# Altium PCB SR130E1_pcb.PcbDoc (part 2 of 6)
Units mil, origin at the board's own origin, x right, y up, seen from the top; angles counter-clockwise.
Board outline 5700 x 4800 mil, 6 copper layers (Top Layer, Signal Layer 1, Signal Layer 2, Signal Layer 3, Signal Layer 4, Bottom Layer), stack 61.4 mil thick; 452 components, 288 nets, 1391 pads, 911 vias.
Unrouted connection lines stored in the file: 523.
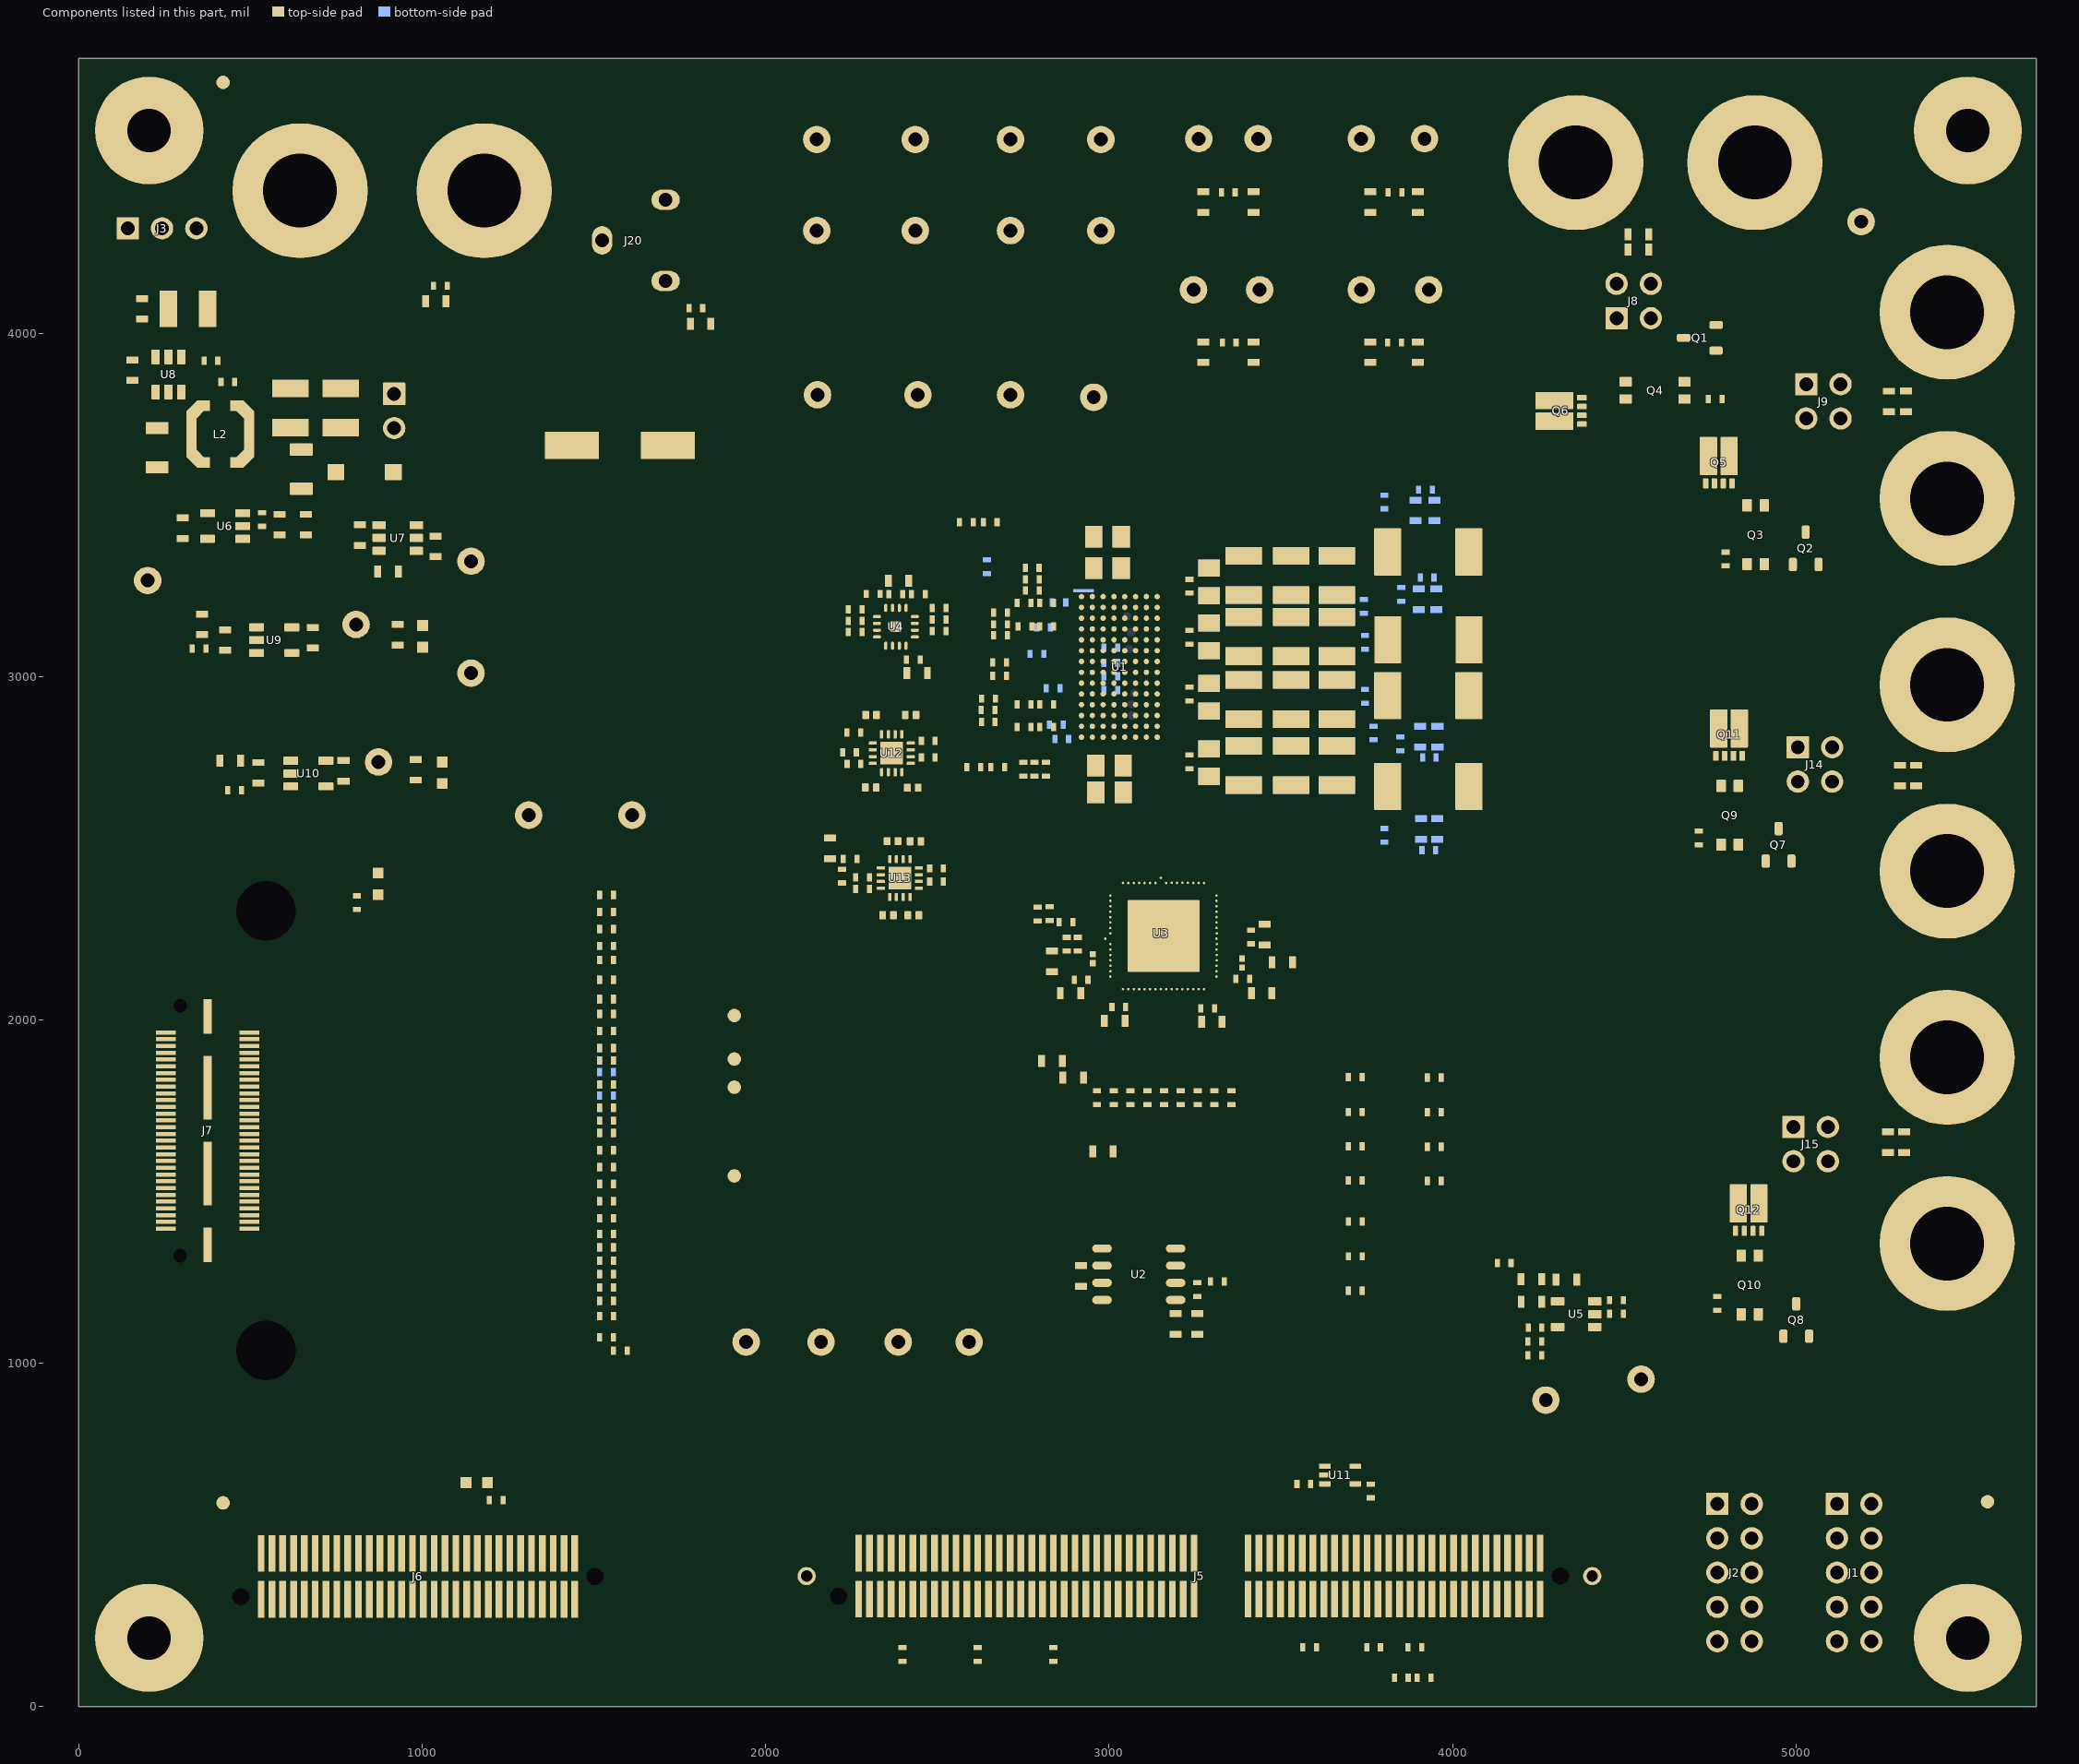
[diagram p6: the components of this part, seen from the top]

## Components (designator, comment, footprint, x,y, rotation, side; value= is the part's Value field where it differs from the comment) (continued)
R165 "CRCW040222R0JNED" 0402S 1537.09,2215.27 r180 top value=22
R166 "CRCW040222R0JNED" 0402S 1537.09,2264.82 r180 top value=22
R167 "CRCW040222R0JNED" 0402S 1537.09,2314.38 r180 top value=22
R168 "CRCW040222R0JNED" 0402S 1537.09,2363.94 r180 top value=22
R169 "ERA-2AEB102X" 0402S 810,2341.09 r270 top value=1.00k
R170 "CRCW040222R0JNED" 0402S 1537.09,1136.86 r0 top value=22
R171 "CRCW040222R0JNED" 0402S 1537.09,1181.96 r0 top value=22
R172 "CRCW040222R0JNED" 0402S 1537.09,1220.76 r0 top value=22
R173 "CRCW040222R0JNED" 0402S 1537.09,1259.57 r0 top value=22
R174 "CRCW040222R0JNED" 0402S 1537.09,1298.37 r0 top value=22
R175 "CRCW040222R0JNED" 0402S 1537.09,1337.17 r0 top value=22
R176 "CRCW040222R0JNED" 0402S 1537.09,1375.98 r0 top value=22
R177 "CRCW040210K0FKED" 0402S 1537.16,1075.74 r0 top value=10.0k
R178 "CRCW040210K0FKED" 0402S 1577.16,1036.74 r0 top value=10.0k
R179 "CRCW0402150RFKED" 0402S 4765.24,3808.24 r0 top value=150
R180 "CRCW0402150RFKED" 0402S 4794.85,3342.02 r90 top value=150
R181 "CRCW0402150RFKED" 0402S 4717.32,2529.51 r90 top value=150
R182 "CRCW0402150RFKED" 0402S 4771.02,1174.56 r90 top value=150
R183 "CRCW04020000Z0ED" 0402S 2256.86,2836.21 r180 top value=0
R184 "CRCW04020000Z0ED" 0402S 2473.63,2764.07 r0 top value=0
R185 "CRCW04020000Z0ED" 0402S 2473.63,2812.05 r0 top value=0
R186 "CRCW04020000Z0ED" 0402S 2257.36,2745.52 r180 top value=0
R187 "RT0603BRD0710KL" 0603S 2187.16,2499.47 r270 top value=10.0k
R188 "CRCW0402866RFKED" 0402S 2223.16,2418.62 r90 top value=866
R189 "CRCW04020000Z0ED" 0402S 2246.37,2468.39 r180 top value=0
R190 "CRCW04020000Z0ED" 0402S 2497.98,2402.93 r0 top value=0
R191 "CRCW04020000Z0ED" 0402S 2497.98,2441.05 r0 top value=0
R192 "CRCW04020000Z0ED" 0402S 2282.79,2380.87 r180 top value=0
SH-J1 "60900213421" Wurth_60900213421 295.19,4304.95 r0 top
SH-J2 "60900213421" Wurth_60900213421 918.65,3773.18 r90 top
SH-J3 "60900213421" Wurth_60900213421 5080.41,3857.59 r180 top
SH-J4 "60900213421" Wurth_60900213421 5081.16,3738.6 r180 top
SH-J5 "60900213421" Wurth_60900213421 4590,4093.27 r90 top
SH-J6 "60900213421" Wurth_60900213421 5043.38,1697.08 r180 top
SH-J7 "60900213421" Wurth_60900213421 5057.41,2685.87 r180 top
SH-J8 "60900213421" Wurth_60900213421 5058.09,2807.52 r180 top
SH-J9 "60900213421" Wurth_60900213421 4467.79,4093.27 r90 top
SH-J10 "60900213421" Wurth_60900213421 5042.98,1573 r180 top
TP1 "5000" Keystone5000 3261.15,4566.08 r90 top
TP2 "5001" Keystone5001 3434.13,4566.08 r90 top
TP3 "SYNC" Keystone5004 2713.15,3820.18 r90 top
TP4 "AGND" Keystone5001 2443.41,3820.18 r90 top
TP5 "5000" Keystone5000 3246.05,4126.08 r90 top
TP6 "5001" Keystone5001 3438.75,4126.08 r90 top
TP7 "SYNC_OUT" Keystone5004 2151.38,3820.18 r90 top
TP8 "5000" Keystone5000 3734.37,4566.08 r90 top
TP9 "5001" Keystone5001 3918.76,4566.08 r90 top
TP10 "5001" Keystone5001 2955.47,3813.25 r0 top
TP11 "5001" Keystone5001 5189.9,4324.34 r0 top
TP12 "5000" Keystone5000 3734.37,4126.08 r90 top
TP13 "5001" Keystone5001 3930.99,4126.08 r90 top
TP14 "LSEN1+" Keystone5004 2149.07,4563.77 r90 top
TP15 "LSEN3+" Keystone5004 2713.15,4563.77 r90 top
TP16 "LSEN2+" Keystone5004 2435.98,4563.77 r90 top
TP17 "LSEN4+" Keystone5004 2976.27,4563.77 r90 top
TP18 "5001" Keystone5001 2149.07,4298.34 r0 top
TP19 "5001" Keystone5001 2435.98,4298.34 r0 top
TP20 "5001" Keystone5001 2713.15,4298.34 r0 top
TP21 "5001" Keystone5001 2976.27,4298.34 r0 top
TP22 "TP_SM_1MM" TP_SM_1MM 1908.94,1885.63 r0 top
TP23 "TP_SM_1MM" TP_SM_1MM 1908.94,1545.46 r0 top
TP24 "TP_SM_1MM" TP_SM_1MM 1908.94,2012.51 r90 top
TP25 "TP_SM_1MM" TP_SM_1MM 1908.94,1803.66 r90 top
TP26 "5000" Keystone5000 1611.19,2596.17 r0 top
TP27 "5000" Keystone5000 4271.89,892.68 r90 top
TP28 "5001" Keystone5001 4549.33,953.44 r0 top
TP29 "5000" Keystone5000 200.79,3279.56 r270 top
TP30 "5000" Keystone5000 1142.39,3335.51 r0 top
TP31 "5000" Keystone5000 807.72,3151.35 r90 top
TP32 "5000" Keystone5000 872.97,2750.87 r90 top
TP33 "5001" Keystone5001 1943.28,1061.66 r90 top
TP34 "5001" Keystone5001 1310.34,2596.17 r90 top
TP35 "5001" Keystone5001 2592.83,1061.66 r90 top
TP36 "5001" Keystone5001 2386.33,1061.66 r90 top
TP37 "5001" Keystone5001 2161.65,1061.66 r90 top
TP38 "5001" Keystone5001 1142.39,3009.58 r90 top
U1 "TPSM8F7620AOGR" APG0112A-MFG 3030.07,3027.87 r90 top
U2 "REF5040AIDR" D0008A_N 3086.96,1259.14 r0 top
U3 "ADS9324RSK" RSK0064B-MFG 3158.7,2244.06 r270 top
U4 "DAC80508MRTET" RTE0016D 2379.47,3144.61 r180 top
U5 "OPA192IDBVT" DBV0005A_N 4360.51,1142.68 r180 top
U6 "TPS7A2050PDBVR" DBV0005A-MFG 426.32,3438.02 r180 top
U7 "LM2664M6" DBV0006A_N 929.09,3403.33 r180 top
U8 "LMR54410DBVR" DBV0006A-MFG 261.28,3879.5 r90 top
U9 "TPS7A2033PDBVR" DBV0005A-MFG 569.38,3105.86 r0 top
U10 "TPS7A2018PDBVR" DBV0005A-MFG 668.88,2717.4 r0 top
U11 "TMP235DCK" DCK0005A_N 3673.04,674.26 r0 top
U12 "OPA4990IRTER" RTE0016C-MFG 2367.3,2776.48 r0 top
U13 "OPA4990IRTER" RTE0016C-MFG 2390.91,2412.78 r0 top
ZZ1 "This Assembly Note is for PCB labels only" AssemblyNoteLabel 469.91,-566 r0 top
ZZ2 "These assemblies are ESD sensitive, ESD precautions shall be observed." AssemblyNote 469.91,-666 r0 top
ZZ3 "These assemblies must be clean and free from flux and all contaminants. Use of no clean flux is not acceptable." AssemblyNote 469.91,-766 r0 top
ZZ4 "These assemblies must comply with workmanship standards IPC-A-610 Class 2, unless otherwise specified." AssemblyNote 469.91,-866 r0 top

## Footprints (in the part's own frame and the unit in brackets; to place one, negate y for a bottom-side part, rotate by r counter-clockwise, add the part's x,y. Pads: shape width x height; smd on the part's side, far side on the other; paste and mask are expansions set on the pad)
0201 [mm] "Data from Kemet datasheet CC101_COM dated 7/28/11"
  rect 0.46x0.42 smd: 1(-0.33,0) 2(0.33,0)
  silkscreen extent -0.25,-0.41 0.25,0.41, body extent -0.31,-0.16 0.31,0.16, height 0.26
0402S [mil] "Based on C0402S footprint from PADS legacy"
  rect 15x24 smd: 1(-20,0) 2(20,0)
  body extent -22,-12 22,12, height 24
0603S [mil]
  rect 20x35 smd: 1(-30,0) 2(30,0)
  body extent -34,-19 34,19, height 39
0805_HV#1 [mil] "0805 with 30mil clearance between pads"
  rect 50x63 smd: 1(-40,0) 2(40,0)
  body extent -43,-29 43,29, height 57
0805_HV#2 [mil] "0805 with 30mil clearance between pads"
  rect 47.24x63 smd: 1(-40,0) 2(40,0)
  body extent -43,-29 43,29, height 57
1210 [mm] "1210 from SM-752 data"
  rect 1.3x2.7 smd: 1(-1.45,0) 2(1.45,0)
  silkscreen extent -2.32,-1.57 2.32,1.57, body extent -1.7,-1.35 1.7,1.35, height 1.35
1210_270 [mm] "1210"
  rect 1.3x2.7 smd: 1(-1.45,0) 2(1.45,0)
  body extent -1.7,-1.35 1.7,1.35, height 2.7
1806_HighSpeed [mm] "Wurth recommended land pattern"
  rrect8% 1.25x1.2 smd: 1(-2.125,0) 2(2.125,0)
  silkscreen extent -1.5,-1 1.5,1, body extent -2.25,-0.8 2.25,0.8, height 1.61
APG0112A-MFG [mm]
  round 0.4 smd paste+0 mask+0.05: A1(-5.2,2.8) A2(-4.4,2.8) A3(-3.6,2.8) A4(-2.8,2.8) A5(-2,2.8) A6(-1.2,2.8) A7(-0.4,2.8) A8(0.4,2.8) A9(1.2,2.8) A10(2,2.8) A11(2.8,2.8) A12(3.6,2.8) A13(4.4,2.8) A14(5.2,2.8) B1(-5.2,2) B2(-4.4,2) B3(-3.6,2) B4(-2.8,2) B5(-2,2) B6(-1.2,2) B7(-0.4,2) B8(0.4,2) B9(1.2,2) B10(2,2) B11(2.8,2) B12(3.6,2) B13(4.4,2) B14(5.2,2) C1(-5.2,1.2) C2(-4.4,1.2) C3(-3.6,1.2) C4(-2.8,1.2) C5(-2,1.2) C6(-1.2,1.2) C7(-0.4,1.2) C8(0.4,1.2) C9(1.2,1.2) C10(2,1.2) C11(2.8,1.2) C12(3.6,1.2) C13(4.4,1.2) C14(5.2,1.2) D1(-5.2,0.4) D2(-4.4,0.4) D3(-3.6,0.4) D4(-2.8,0.4) D5(-2,0.4) D6(-1.2,0.4) D7(-0.4,0.4) D8(0.4,0.4) D9(1.2,0.4) D10(2,0.4) D11(2.8,0.4) D12(3.6,0.4) D13(4.4,0.4) D14(5.2,0.4) E1(-5.2,-0.4) E2(-4.4,-0.4) E3(-3.6,-0.4) E4(-2.8,-0.4) E5(-2,-0.4) E6(-1.2,-0.4) E7(-0.4,-0.4) E8(0.4,-0.4) E9(1.2,-0.4) E10(2,-0.4) E11(2.8,-0.4) E12(3.6,-0.4) E13(4.4,-0.4) E14(5.2,-0.4) F1(-5.2,-1.2) F2(-4.4,-1.2) F3(-3.6,-1.2) F4(-2.8,-1.2) F5(-2,-1.2) F6(-1.2,-1.2) F7(-0.4,-1.2) F8(0.4,-1.2) F9(1.2,-1.2) F10(2,-1.2) F11(2.8,-1.2) F12(3.6,-1.2) F13(4.4,-1.2) F14(5.2,-1.2) G1(-5.2,-2) G2(-4.4,-2) G3(-3.6,-2) G4(-2.8,-2) G5(-2,-2) G6(-1.2,-2) G7(-0.4,-2) G8(0.4,-2) G9(1.2,-2) G10(2,-2) G11(2.8,-2) G12(3.6,-2) G13(4.4,-2) G14(5.2,-2) H1(-5.2,-2.8) H2(-4.4,-2.8) H3(-3.6,-2.8) H4(-2.8,-2.8) H5(-2,-2.8) H6(-1.2,-2.8) H7(-0.4,-2.8) H8(0.4,-2.8) H9(1.2,-2.8) H10(2,-2.8) H11(2.8,-2.8) H12(3.6,-2.8) H13(4.4,-2.8) H14(5.2,-2.8)
  silkscreen extent -6.67,-3.57 6.07,3.57, body extent -6.58,-4.08 6.58,4.08, height 0.25
AssemblyNote [mil] "Assembly Note"
AssemblyNoteLabel [mil] "Assembly Note for PCB Labels"
CE_Mark_5mm [mil] "Minimum text height for CE Mark"
  silkscreen extent -138,-98 138,98
CONN_PJ-102A [mm] "CUI INC"
  oval 1.5x2.1 hole 1 slot 1.6 at 90 deg: 1(-3,0) 2(3,0)
  oval 2.1x1.5 hole 1 slot 1.6 at 0 deg: 3(0,4.7)
  silkscreen extent -3.7,-4.5 10.7,4.9, body extent -3.7,-4.5 10.7,4.9, height 11.02
controlCARD-120HSEC [mm] "Pads are not numbered according to Samtec datasheet."
  rect 0.5x2.724 smd: 1(-23.357,-1.678) 2(-23.357,1.722) 3(-22.557,-1.678) 4(-22.557,1.722) 5(-21.757,-1.678) 6(-21.757,1.722) 7(-20.957,-1.678) 8(-20.957,1.722) 9(-20.157,-1.678) 10(-20.157,1.722) 11(-19.357,-1.678) 12(-19.357,1.722) 13(-18.557,-1.678) 14(-18.557,1.722) 15(-17.757,-1.678) 16(-17.757,1.722) 17(-16.957,-1.678) 18(-16.957,1.722) 19(-16.157,-1.678) 20(-16.157,1.722) 21(-15.357,-1.678) 22(-15.357,1.722) 23(-14.557,-1.678) 24(-14.557,1.722) 25(-13.757,-1.678) 26(-13.757,1.722) 27(-12.957,-1.678) 28(-12.957,1.722) 29(-12.157,-1.678) 30(-12.157,1.722) 31(-11.357,-1.678) 32(-11.357,1.722) 33(-10.557,-1.678) 34(-10.557,1.722) 35(-9.757,-1.678) 36(-9.757,1.722) 37(-8.957,-1.678) 38(-8.957,1.722) 39(-8.157,-1.678) 40(-8.157,1.722) 41(-7.357,-1.678) 42(-7.357,1.722) 43(-6.557,-1.678) 44(-6.557,1.722) 45(-5.757,-1.678) 46(-5.757,1.722) 47(-4.957,-1.678) 48(-4.957,1.722) 49(-4.157,-1.678) 50(-4.157,1.722) 51(-3.357,-1.678) 52(-3.357,1.722) 53(-2.557,-1.678) 54(-2.557,1.722) 55(-1.757,-1.678) 56(-1.757,1.722) 57(2.243,-1.678) 58(2.243,1.722) 59(3.043,-1.678) 60(3.043,1.722) 61(3.843,-1.678) 62(3.843,1.722) 63(4.643,-1.678) 64(4.643,1.722) 65(5.443,-1.678) 66(5.443,1.722) 67(6.243,-1.678) 68(6.243,1.722) 69(7.043,-1.678) 70(7.043,1.722) 71(7.843,-1.678) 72(7.843,1.722) 73(8.643,-1.678) 74(8.643,1.722) 75(9.443,-1.678) 76(9.443,1.722) 77(10.243,-1.678) 78(10.243,1.722) 79(11.043,-1.678) 80(11.043,1.722) 81(11.843,-1.678) 82(11.843,1.722) 83(12.643,-1.678) 84(12.643,1.722) 85(13.443,-1.678) 86(13.443,1.722) 87(14.243,-1.678) 88(14.243,1.722) 89(15.043,-1.678) 90(15.043,1.722) 91(15.843,-1.678) 92(15.843,1.722) 93(16.643,-1.678) 94(16.643,1.722) 95(17.443,-1.678) 96(17.443,1.722) 97(18.243,-1.678) 98(18.243,1.722) 99(19.043,-1.678) 100(19.043,1.722) 101(19.843,-1.678) 102(19.843,1.722) 103(20.643,-1.678) 104(20.643,1.722) 105(21.443,-1.678) 106(21.443,1.722) 107(22.243,-1.678) 108(22.243,1.722) 109(23.043,-1.678) 110(23.043,1.722) 111(23.843,-1.678) 112(23.843,1.722) 113(24.643,-1.678) 114(24.643,1.722) 115(25.443,-1.678) 116(25.443,1.722) 117(26.243,-1.678) 118(26.243,1.722) 119(27.043,-1.678) 120(27.043,1.722)
  round 0.025 hole 1.27 unplated mask+0.876: 181(-24.857,0.022) 182(28.543,1.522)
  round 1.348 hole 0.84: 185(-27.207,0.022) 186(30.893,0.022)
  silkscreen extent -32.11,-3.86 35.8,3.9, body extent -31.75,-3.48 35.3,3.52, height 12.35
controlCARD-180HSEC-60pinAddon [mm] "Pads are not numbered according to datasheet."
  round 0.025 hole 1.27 unplated mask+0.876: 61(-13.1,0) 62(13.1,1.5)
  rect 0.5x2.724 smd: 121(-11.6,-1.7) 122(-11.6,1.7) 123(-10.8,-1.7) 124(-10.8,1.7) 125(-10,-1.7) 126(-10,1.7) 127(-9.2,-1.7) 128(-9.2,1.7) 129(-8.4,-1.7) 130(-8.4,1.7) 131(-7.6,-1.7) 132(-7.6,1.7) 133(-6.8,-1.7) 134(-6.8,1.7) 135(-6,-1.7) 136(-6,1.7) 137(-5.2,-1.7) 138(-5.2,1.7) 139(-4.4,-1.7) 140(-4.4,1.7) 141(-3.6,-1.7) 142(-3.6,1.7) 143(-2.8,-1.7) 144(-2.8,1.7) 145(-2,-1.7) 146(-2,1.7) 147(-1.2,-1.7) 148(-1.2,1.7) 149(-0.4,-1.7) 150(-0.4,1.7) 151(0.4,-1.7) 152(0.4,1.7) 153(1.2,-1.7) 154(1.2,1.7) 155(2,-1.7) 156(2,1.7) 157(2.8,-1.7) 158(2.8,1.7) 159(3.6,-1.7) 160(3.6,1.7) 161(4.4,-1.7) 162(4.4,1.7) 163(5.2,-1.7) 164(5.2,1.7) 165(6,-1.7) 166(6,1.7) 167(6.8,-1.7) 168(6.8,1.7) 169(7.6,-1.7) 170(7.6,1.7) 171(8.4,-1.7) 172(8.4,1.7) 173(9.2,-1.7) 174(9.2,1.7) 175(10,-1.7) 176(10,1.7) 177(10.8,-1.7) 178(10.8,1.7) 179(11.6,-1.7) 180(11.6,1.7)
  silkscreen extent -14.68,-3.88 14.68,3.88, body extent -14.3,-3.5 14.3,3.5, height 7.95
D0008A_N [mm] "SOIC, 8-Leads, Body 4.9x3.9mm, Pitch 1.27mm, IPC Medium Density"
  oval 1.45x0.6 smd: 1(-2.725,1.905) 2(-2.725,0.635) 3(-2.725,-0.635) 4(-2.725,-1.905) 5(2.725,-1.905) 6(2.725,-0.635) 7(2.725,0.635) 8(2.725,1.905)
  silkscreen extent -3.3,-2.5 0.9,2.5, body extent -3,-2.45 3,2.45, height 1.63
DBV0005A-MFG [mm]
  rrect17% 1.1x0.6 smd paste+0 mask+0: 1(-1.3,0.95) 2(-1.3,0) 3(-1.3,-0.95) 4(1.3,-0.95) 5(1.3,0.95)
  silkscreen extent -2.58,-1.53 0.87,1.53, body extent -1.95,-1.78 1.95,1.78, height 0.25
DBV0005A_N [mm] "SOT23, 5-Leads, Body 2.9x1.6mm, Pitch 0.95mm, Lead Span 2.8mm, IPC Medium Density"
  rrect17% 1x0.6 smd: 1(-1.375,0.95) 2(-1.375,0) 3(-1.375,-0.95) 4(1.375,-0.95) 5(1.375,0.95)
  silkscreen extent -0.25,-1.55 0.25,1.55, body extent -1.42,-1.46 1.42,1.46, height 1.09
DBV0006A-MFG [mm]
  rrect17% 1.1x0.6 smd paste+0 mask+0: 1(-1.3,0.95) 2(-1.3,0) 3(-1.3,-0.95) 4(1.3,-0.95) 5(1.3,0) 6(1.3,0.95)
  silkscreen extent -2.52,-1.53 0.35,1.53, body extent -1.95,-1.78 1.95,1.78, height 0.25
DBV0006A_N [mm] "SOT23, 6-Leads, Body 2.9x1.6mm, Pitch 0.95mm, Lead Span 2.8mm, IPC Medium Density"
  rrect17% 1x0.6 smd: 1(-1.375,0.95) 2(-1.375,0) 3(-1.375,-0.95) 4(1.375,-0.95) 5(1.375,0) 6(1.375,0.95)
  silkscreen extent -1.68,-1.55 0.5,1.55, body extent -1.42,-1.46 1.42,1.46, height 1.12
DCK0005A_N [mm] "SOT353, 5-Leads, Body 2x1.3mm, Pitch 0.65mm, Lead Span 2.1mm, IPC Medium Density"
  rrect25% 0.85x0.4 smd: 1(-1.125,0.65) 2(-1.125,0) 3(-1.125,-0.65) 4(1.125,-0.65) 5(1.125,0.65)
  silkscreen extent -1.48,-1.02 0.55,1.1, body extent -1.14,-1 1.14,1, height 0.95
DTD0008A-MFG [mm] "Recommended Land Pattern"
  rrect25% 0.73x0.4 smd paste-1000 mask-1000: 1(-1.535,0.975) 2(-1.535,0.325) 3(-1.535,-0.325) 4(-1.535,-0.975)
  rrect33% 0.545x0.3 smd paste+0 mask-1000: 5(1.578,-0.975) 6(1.578,-0.325) 7(1.578,0.325) 8(1.578,0.975)
  rrect8% 2.82x1.28 smd paste-1000 mask-1000: 9(0.49,0.763) 10(0.49,-0.763)
  silkscreen extent -2.52,-1.7 1.7,1.7, body extent -1.65,-1.65 1.65,1.65, height 1
FCC_disclaimer [mil]
Fiducial10-20 [mm]
  round 1 smd mask+0.5: 1(0,0)
  Top Layer keep-out circle w1.178: c0,0 r0.5
FP-1N4148WL2-TP_DFN1006-MFG [mm] "Recommended Land Pattern"
  rrect20% 0.5x0.6 smd paste+0 mask+0: 1(-0.4,0) 2(0.4,0)
  silkscreen extent -1.33,-0.67 0.53,0.67, body extent -0.5,-0.3 0.5,0.3, height 0.5
FP-APV2111VY_SSOP4-MFG [mm] "Recommended Land Pattern"
  rrect14% 0.9x0.7 smd paste+0 mask+0: 1(-2.175,0.635) 2(-2.175,-0.635) 3(2.175,-0.635) 4(2.175,0.635)
  silkscreen extent -3.2,-1.38 2.27,1.38, body extent -2.42,-1.33 2.42,1.33, height 1.9
FP-CRCW12060000Z0EAC_1206-MFG [mm]
  rrect11% 0.9x1.7 smd paste+0 mask+0: 1(-1.45,0) 2(1.45,0)
  silkscreen extent -0.63,-0.82 0.63,0.82, body extent -2,-0.95 2,0.95, height 0.25
FP-TLRP3A20CR080FTE_2512-MFG [mm] "Recommended Land Pattern"
  rrect5% 2x3.5 smd paste+0 mask+0: 1(-3,0) 2(3,0)
  silkscreen extent -1.63,-1.73 1.63,1.73, body extent -3.2,-1.6 3.2,1.6, height 0.9
IEC_HotSurface_Medium [mil]
  silkscreen extent -217,-188 217,188
Keystone5000 [mil] "For Keystone 500x miniature loop terminals"
  round 80 hole 40: 1(0,0)
  silkscreen extent -52,-52 52,52, body extent -49,-49 49,49, height 182
Keystone5001 [mil] "For Keystone 500x miniature loop terminals"
  round 80 hole 40: 1(0,0)
  silkscreen extent -52,-52 52,52, body extent -49,-49 49,49, height 182
Keystone5004 [mil] "For Keystone 500x miniature loop terminals"
  round 80 hole 40: 1(0,0)
  silkscreen extent -52,-52 52,52, body extent -49,-49 49,49, height 182
Keystone_575-4 [mm] "Banana Jack"
  round 10 hole 5.45: 1(0,0)
  body extent -3.95,-3.95 3.92,3.93, height 2.36
Keystone_1902C [mil] "Hex Standoff, 4-40 threaded, nylon"
  round 1 on Mech4: 0(0,0)
  body extent -145,-126 146,126, height 501
Label_650x200 [mil] "Thermal Transfer Label"
  round 1 on Mech13: 0(0,0)
  silkscreen extent -325,-100 325,100, body extent -325,-100 325,100, height 1
LPS5015 [mm] "Coilcraft recommended land pattern.  Document 585-2, rev 12/05/08"
  rect 0.75x3.4 smd: 1(-2.125,0) 2(2.125,0)
  rect 1.131x0.92 smd rot 135: 1(-1.776,-1.776) 2(1.776,1.776)
  rect 1.131x0.92 smd rot 45: 1(-1.776,1.776) 2(1.776,-1.776)
  rect 0.95x0.8 smd: 1(-1.225,-2.1) 1(-1.225,2.1) 2(1.225,-2.1) 2(1.225,2.1)
  silkscreen extent -3.45,-2.8 2.8,2.8, body extent -2.5,-2.5 2.51,2.51, height 1.52
Net-Tie_10milWide_30milLong [mil] "10mil net tie, no solder mask opening, no solder paste"
  rect 30x10 smd paste-5 mask-5: 1(-15,0) 2(15,0)
"NY PMS 440 0025 PH" [mm] "4-40 nylon screw and mounting hole"
  round 8 hole 3.2: 1(0,0)
  body extent -3.31,-3.3 3.3,3.3, height 2.69
RSK0064B-MFG [mm] "Recommended Land Pattern"
  round 0.18 smd paste-1000 mask+0: 1(-3.925,3) 2(-3.925,2.6) 3(-3.925,2.2) 4(-3.935,1.8) 5(-3.935,1.4) 6(-3.925,1) 7(-3.935,0.6) 8(-3.925,0.2) 9(-4.3,-0.2) 10(-3.925,-0.6) 11(-3.925,-1) 12(-3.925,-1.4) 13(-3.925,-1.8) 14(-3.925,-2.2) 15(-3.925,-2.6) 16(-3.925,-3) 17(-3,-3.925) 18(-2.6,-3.925) 19(-2.2,-3.925) 20(-1.8,-3.935) 21(-1.4,-3.935) 22(-1,-3.925) 23(-0.6,-3.935) 24(-0.2,-3.925) 25(0.2,-4.3) 26(0.6,-3.925) 27(1,-3.925) 28(1.4,-3.925) 29(1.8,-3.925) 30(2.2,-3.925) 31(2.6,-3.925) 32(3,-3.925) 33(3.925,-3) 34(3.925,-2.6) 35(3.925,-2.2) 36(3.935,-1.8) 37(3.935,-1.4) 38(3.925,-1) 39(3.935,-0.6) 40(3.925,-0.2) 41(3.935,0.2) 42(3.925,0.6) 43(3.925,1) 44(3.925,1.4) 45(3.925,1.8) 46(3.925,2.2) 47(3.925,2.6) 48(3.925,3) 49(3,3.925) 50(2.6,3.925) 51(2.2,3.925) 52(1.8,3.935) 53(1.4,3.935) 54(1,3.925) 55(0.6,3.935) 56(0.2,3.925) 57(-0.2,3.935) 58(-0.6,3.925) 59(-1,3.925) 60(-1.4,3.925) 61(-1.8,3.925) 62(-2.2,3.925) 63(-2.6,3.925) 64(-3,3.925)
  rrect2% 5.31x5.31 smd paste-1000 mask+0: 65(0,0)
  Top Layer region: -2.9,4.4 -2.9,3.55 -2.913,3.5 -2.95,3.463 -3,3.45 -3,3.45 -3.038,3.458 -3.071,3.479 -3.092,3.512 -3.1,3.55 -3.1,3.55 -3.1,4.4
  Top Layer region: -2.5,4.4 -2.5,3.55 -2.508,3.512 -2.529,3.479 -2.562,3.458 -2.6,3.45 -2.6,3.45 -2.638,3.458 -2.671,3.479 -2.692,3.512 -2.7,3.55 -2.7,3.55 -2.7,4.4
  Top Layer region: -2.1,4.4 -2.1,3.55 -2.113,3.5 -2.15,3.463 -2.2,3.45 -2.2,3.45 -2.238,3.458 -2.271,3.479 -2.292,3.512 -2.3,3.55 -2.3,3.55 -2.3,4.4
  Top Layer region: -1.7,4.4 -1.7,3.55 -1.713,3.5 -1.75,3.463 -1.8,3.45 -1.8,3.45 -1.838,3.458 -1.871,3.479 -1.892,3.512 -1.9,3.55 -1.9,3.55 -1.9,4.4
  Top Layer region: -1.3,4.4 -1.3,3.55 -1.313,3.5 -1.35,3.463 -1.4,3.45 -1.4,3.45 -1.438,3.458 -1.471,3.479 -1.492,3.512 -1.5,3.55 -1.5,3.55 -1.5,4.4
  Top Layer region: -0.9,4.4 -0.9,3.55 -0.908,3.512 -0.929,3.479 -0.962,3.458 -1,3.45 -1,3.45 -1.038,3.458 -1.071,3.479 -1.092,3.512 -1.1,3.55 -1.1,3.55 -1.1,4.4
  Top Layer region: -0.5,4.4 -0.5,3.55 -0.513,3.5 -0.55,3.463 -0.6,3.45 -0.6,3.45 -0.638,3.458 -0.671,3.479 -0.692,3.512 -0.7,3.55 -0.7,3.55 -0.7,4.4
  Top Layer region: -0.1,4.4 -0.1,3.55 -0.108,3.512 -0.129,3.479 -0.162,3.458 -0.2,3.45 -0.2,3.45 -0.238,3.458 -0.271,3.479 -0.292,3.512 -0.3,3.55 -0.3,3.55 -0.3,4.4
  Top Layer region: 0.3,4.4 0.3,3.55 0.292,3.512 0.271,3.479 0.238,3.458 0.2,3.45 0.2,3.45 0.162,3.458 0.129,3.479 0.108,3.512 0.1,3.55 0.1,3.55 0.1,4.4
  Top Layer region: 0.7,4.4 0.7,3.55 0.687,3.5 0.65,3.463 0.6,3.45 0.6,3.45 0.562,3.458 0.529,3.479 0.508,3.512 0.5,3.55 0.5,3.55 0.5,4.4
  Top Layer region: 1.1,4.4 1.1,3.55 1.087,3.5 1.05,3.463 1,3.45 1,3.45 0.962,3.458 0.929,3.479 0.908,3.512 0.9,3.55 0.9,3.55 0.9,4.4
  Top Layer region: 1.5,4.4 1.5,3.55 1.487,3.5 1.45,3.463 1.4,3.45 1.4,3.45 1.362,3.458 1.329,3.479 1.308,3.512 1.3,3.55 1.3,3.55 1.3,4.4
  Top Layer region: 1.9,4.4 1.9,3.55 1.887,3.5 1.85,3.463 1.8,3.45 1.8,3.45 1.762,3.458 1.729,3.479 1.708,3.512 1.7,3.55 1.7,3.55 1.7,4.4
  Top Layer region: 2.3,4.4 2.3,3.55 2.287,3.5 2.25,3.463 2.2,3.45 2.2,3.45 2.162,3.458 2.129,3.479 2.108,3.512 2.1,3.55 2.1,3.55 2.1,4.4
  Top Layer region: 2.1,-4.4 2.1,-3.55 2.108,-3.512 2.129,-3.479 2.162,-3.458 2.2,-3.45 2.2,-3.45 2.238,-3.458 2.271,-3.479 2.292,-3.512 2.3,-3.55 2.3,-3.55 2.3,-4.4
  Top Layer region: 1.7,-4.4 1.7,-3.55 1.708,-3.512 1.729,-3.479 1.762,-3.458 1.8,-3.45 1.8,-3.45 1.838,-3.458 1.871,-3.479 1.892,-3.512 1.9,-3.55 1.9,-3.55 1.9,-4.4
  Top Layer region: 1.3,-4.4 1.3,-3.55 1.308,-3.512 1.329,-3.479 1.362,-3.458 1.4,-3.45 1.4,-3.45 1.438,-3.458 1.471,-3.479 1.492,-3.512 1.5,-3.55 1.5,-3.55 1.5,-4.4
  Top Layer region: 0.9,-4.4 0.9,-3.55 0.908,-3.512 0.929,-3.479 0.962,-3.458 1,-3.45 1,-3.45 1.038,-3.458 1.071,-3.479 1.092,-3.512 1.1,-3.55 1.1,-3.55 1.1,-4.4
  Top Layer region: 0.5,-4.4 0.5,-3.55 0.508,-3.512 0.529,-3.479 0.562,-3.458 0.6,-3.45 0.6,-3.45 0.638,-3.458 0.671,-3.479 0.692,-3.512 0.7,-3.55 0.7,-3.55 0.7,-4.4
  Top Layer region: 0.1,-4.4 0.1,-3.55 0.108,-3.512 0.129,-3.479 0.162,-3.458 0.2,-3.45 0.2,-3.45 0.238,-3.458 0.271,-3.479 0.292,-3.512 0.3,-3.55 0.3,-3.55 0.3,-4.4
  Top Layer region: -0.3,-4.4 -0.3,-3.55 -0.292,-3.512 -0.271,-3.479 -0.238,-3.458 -0.2,-3.45 -0.2,-3.45 -0.162,-3.458 -0.129,-3.479 -0.108,-3.512 -0.1,-3.55 -0.1,-3.55 -0.1,-4.4
  Top Layer region: -1.1,-4.4 -1.1,-3.55 -1.092,-3.512 -1.071,-3.479 -1.038,-3.458 -1,-3.45 -1,-3.45 -0.962,-3.458 -0.929,-3.479 -0.908,-3.512 -0.9,-3.55 -0.9,-3.55 -0.9,-4.4
  Top Layer region: -1.9,-4.4 -1.9,-3.55 -1.892,-3.512 -1.871,-3.479 -1.838,-3.458 -1.8,-3.45 -1.8,-3.45 -1.762,-3.458 -1.729,-3.479 -1.708,-3.512 -1.7,-3.55 -1.7,-3.55 -1.7,-4.4
  Top Layer region: -2.7,-4.4 -2.7,-3.55 -2.692,-3.512 -2.671,-3.479 -2.638,-3.458 -2.6,-3.45 -2.6,-3.45 -2.562,-3.458 -2.529,-3.479 -2.508,-3.512 -2.5,-3.55 -2.5,-3.55 -2.5,-4.4
  Top Layer region: -3.1,-4.4 -3.1,-3.55 -3.092,-3.512 -3.071,-3.479 -3.038,-3.458 -3,-3.45 -3,-3.45 -2.962,-3.458 -2.929,-3.479 -2.908,-3.512 -2.9,-3.55 -2.9,-3.55 -2.9,-4.4
  Top Layer region: 4.4,2.9 3.55,2.9 3.512,2.908 3.479,2.929 3.458,2.962 3.45,3 3.45,3 3.458,3.038 3.479,3.071 3.512,3.092 3.55,3.1 3.55,3.1 4.4,3.1
  Top Layer region: 4.4,2.5 3.55,2.5 3.512,2.508 3.479,2.529 3.458,2.562 3.45,2.6 3.45,2.6 3.458,2.638 3.479,2.671 3.512,2.692 3.55,2.7 3.55,2.7 4.4,2.7
  Top Layer region: 4.4,2.1 3.55,2.1 3.512,2.108 3.479,2.129 3.458,2.162 3.45,2.2 3.45,2.2 3.458,2.238 3.479,2.271 3.512,2.292 3.55,2.3 3.55,2.3 4.4,2.3
  Top Layer region: 4.4,1.7 3.55,1.7 3.512,1.708 3.479,1.729 3.458,1.762 3.45,1.8 3.45,1.8 3.458,1.838 3.479,1.871 3.512,1.892 3.55,1.9 3.55,1.9 4.4,1.9
  Top Layer region: 4.4,1.3 3.55,1.3 3.512,1.308 3.479,1.329 3.458,1.362 3.45,1.4 3.45,1.4 3.458,1.438 3.479,1.471 3.512,1.492 3.55,1.5 3.55,1.5 4.4,1.5
  Top Layer region: 4.4,0.9 3.55,0.9 3.512,0.908 3.479,0.929 3.458,0.962 3.45,1 3.45,1 3.458,1.038 3.479,1.071 3.512,1.092 3.55,1.1 3.55,1.1 4.4,1.1
  Top Layer region: 4.4,0.5 3.55,0.5 3.512,0.508 3.479,0.529 3.458,0.562 3.45,0.6 3.45,0.6 3.458,0.638 3.479,0.671 3.512,0.692 3.55,0.7 3.55,0.7 4.4,0.7
  Top Layer region: 4.4,0.1 3.55,0.1 3.512,0.108 3.479,0.129 3.458,0.162 3.45,0.2 3.45,0.2 3.458,0.238 3.479,0.271 3.512,0.292 3.55,0.3 3.55,0.3 4.4,0.3
  Top Layer region: 4.4,-2.7 3.55,-2.7 3.512,-2.692 3.479,-2.671 3.458,-2.638 3.45,-2.6 3.45,-2.6 3.458,-2.562 3.479,-2.529 3.512,-2.508 3.55,-2.5 3.55,-2.5 4.4,-2.5
  Top Layer region: 4.4,-3.1 3.55,-3.1 3.512,-3.092 3.479,-3.071 3.458,-3.038 3.45,-3 3.45,-3 3.458,-2.962 3.479,-2.929 3.512,-2.908 3.55,-2.9 3.55,-2.9 4.4,-2.9
  Top Layer region: -4.4,-2.9 -3.55,-2.9 -3.512,-2.908 -3.479,-2.929 -3.458,-2.962 -3.45,-3 -3.45,-3 -3.463,-3.05 -3.5,-3.087 -3.55,-3.1 -3.55,-3.1 -4.4,-3.1
  Top Layer region: -4.4,-2.5 -3.55,-2.5 -3.512,-2.508 -3.479,-2.529 -3.458,-2.562 -3.45,-2.6 -3.45,-2.6 -3.458,-2.638 -3.479,-2.671 -3.512,-2.692 -3.55,-2.7 -3.55,-2.7 -4.4,-2.7
  Top Layer region: -4.4,-2.1 -3.55,-2.1 -3.512,-2.108 -3.479,-2.129 -3.458,-2.162 -3.45,-2.2 -3.45,-2.2 -3.458,-2.238 -3.479,-2.271 -3.512,-2.292 -3.55,-2.3 -3.55,-2.3 -4.4,-2.3
  Top Layer region: -4.4,-1.7 -3.55,-1.7 -3.512,-1.708 -3.479,-1.729 -3.458,-1.762 -3.45,-1.8 -3.45,-1.8 -3.463,-1.85 -3.5,-1.887 -3.55,-1.9 -3.55,-1.9 -4.4,-1.9
  Top Layer region: -4.4,-1.3 -3.55,-1.3 -3.512,-1.308 -3.479,-1.329 -3.458,-1.362 -3.45,-1.4 -3.45,-1.4 -3.458,-1.438 -3.479,-1.471 -3.512,-1.492 -3.55,-1.5 -3.55,-1.5 -4.4,-1.5
  Top Layer region: -4.4,-0.9 -3.55,-0.9 -3.512,-0.908 -3.479,-0.929 -3.458,-0.962 -3.45,-1 -3.45,-1 -3.458,-1.038 -3.479,-1.071 -3.512,-1.092 -3.55,-1.1 -3.55,-1.1 -4.4,-1.1
  Top Layer region: -4.4,-0.5 -3.55,-0.5 -3.512,-0.508 -3.479,-0.529 -3.458,-0.562 -3.45,-0.6 -3.45,-0.6 -3.458,-0.638 -3.479,-0.671 -3.512,-0.692 -3.55,-0.7 -3.55,-0.7 -4.4,-0.7
  Top Layer region: -4.4,-0.1 -3.55,-0.1 -3.512,-0.108 -3.479,-0.129 -3.458,-0.162 -3.45,-0.2 -3.45,-0.2 -3.458,-0.238 -3.479,-0.271 -3.512,-0.292 -3.55,-0.3 -3.55,-0.3 -4.4,-0.3
  Top Layer region: -4.4,0.3 -3.55,0.3 -3.512,0.292 -3.479,0.271 -3.458,0.238 -3.45,0.2 -3.45,0.2 -3.458,0.162 -3.479,0.129 -3.512,0.108 -3.55,0.1 -3.55,0.1 -4.4,0.1
  Top Layer region: -4.4,0.7 -3.55,0.7 -3.512,0.692 -3.479,0.671 -3.458,0.638 -3.45,0.6 -3.45,0.6 -3.458,0.562 -3.479,0.529 -3.512,0.508 -3.55,0.5 -3.55,0.5 -4.4,0.5
  Top Layer region: -4.4,1.1 -3.55,1.1 -3.512,1.092 -3.479,1.071 -3.458,1.038 -3.45,1 -3.45,1 -3.458,0.962 -3.479,0.929 -3.512,0.908 -3.55,0.9 -3.55,0.9 -4.4,0.9
  Top Layer region: -4.4,1.5 -3.55,1.5 -3.512,1.492 -3.479,1.471 -3.458,1.438 -3.45,1.4 -3.45,1.4 -3.458,1.362 -3.479,1.329 -3.512,1.308 -3.55,1.3 -3.55,1.3 -4.4,1.3
  Top Layer region: -4.4,1.9 -3.55,1.9 -3.512,1.892 -3.479,1.871 -3.458,1.838 -3.45,1.8 -3.45,1.8 -3.458,1.762 -3.479,1.729 -3.512,1.708 -3.55,1.7 -3.55,1.7 -4.4,1.7
  Top Layer region: -4.4,2.3 -3.55,2.3 -3.512,2.292 -3.479,2.271 -3.458,2.238 -3.45,2.2 -3.45,2.2 -3.463,2.15 -3.5,2.113 -3.55,2.1 -3.55,2.1 -4.4,2.1
  Top Layer region: -4.4,2.7 -3.55,2.7 -3.512,2.692 -3.479,2.671 -3.458,2.638 -3.45,2.6 -3.45,2.6 -3.463,2.55 -3.5,2.513 -3.55,2.5 -3.55,2.5 -4.4,2.5
  Top Layer region: -4.4,3.1 -3.55,3.1 -3.512,3.092 -3.479,3.071 -3.458,3.038 -3.45,3 -3.45,3 -3.463,2.95 -3.5,2.913 -3.55,2.9 -3.55,2.9 -4.4,2.9
  Top Layer region: 4.4,-1.5 3.55,-1.5 3.512,-1.492 3.479,-1.471 3.458,-1.438 3.45,-1.4 3.45,-1.4 3.458,-1.362 3.479,-1.329 3.512,-1.308 3.55,-1.3 3.55,-1.3 4.4,-1.3
  Top Layer region: 4.4,-1.9 3.55,-1.9 3.512,-1.892 3.479,-1.871 3.458,-1.838 3.45,-1.8 3.45,-1.8 3.458,-1.762 3.479,-1.729 3.512,-1.708 3.55,-1.7 3.55,-1.7 4.4,-1.7
  Top Layer region: 4.4,-1.1 3.55,-1.1 3.512,-1.092 3.479,-1.071 3.458,-1.038 3.45,-1 3.45,-1 3.458,-0.962 3.479,-0.929 3.512,-0.908 3.55,-0.9 3.55,-0.9 4.4,-0.9
  Top Layer region: 4.4,-2.3 3.55,-2.3 3.512,-2.292 3.479,-2.271 3.458,-2.238 3.45,-2.2 3.45,-2.2 3.458,-2.162 3.479,-2.129 3.512,-2.108 3.55,-2.1 3.55,-2.1 4.4,-2.1
  Top Layer region: 4.4,-0.3 3.55,-0.3 3.512,-0.292 3.479,-0.271 3.458,-0.238 3.45,-0.2 3.45,-0.2 3.458,-0.162 3.479,-0.129 3.512,-0.108 3.55,-0.1 3.55,-0.1 4.4,-0.1
  Top Layer region: 4.4,-0.7 3.55,-0.7 3.512,-0.692 3.479,-0.671 3.458,-0.638 3.45,-0.6 3.45,-0.6 3.458,-0.562 3.479,-0.529 3.512,-0.508 3.55,-0.5 3.55,-0.5 4.4,-0.5
  Top Layer region: 3.1,4.4 3.1,3.55 3.087,3.5 3.05,3.463 3,3.45 3,3.45 2.962,3.458 2.929,3.479 2.908,3.512 2.9,3.55 2.9,3.55 2.9,4.4
  Top Layer region: 2.7,4.4 2.7,3.55 2.692,3.512 2.671,3.479 2.638,3.458 2.6,3.45 2.6,3.45 2.562,3.458 2.529,3.479 2.508,3.512 2.5,3.55 2.5,3.55 2.5,4.4
  Top Layer region: 2.9,-4.4 2.9,-3.55 2.908,-3.512 2.929,-3.479 2.962,-3.458 3,-3.45 3,-3.45 3.038,-3.458 3.071,-3.479 3.092,-3.512 3.1,-3.55 3.1,-3.55 3.1,-4.4
  Top Layer region: 2.5,-4.4 2.5,-3.55 2.508,-3.512 2.529,-3.479 2.562,-3.458 2.6,-3.45 2.6,-3.45 2.638,-3.458 2.671,-3.479 2.692,-3.512 2.7,-3.55 2.7,-3.55 2.7,-4.4
  Top Layer region: -2.3,-4.4 -2.3,-3.55 -2.292,-3.512 -2.271,-3.479 -2.238,-3.458 -2.2,-3.45 -2.2,-3.45 -2.162,-3.458 -2.129,-3.479 -2.108,-3.512 -2.1,-3.55 -2.1,-3.55 -2.1,-4.4
  Top Layer region: -1.5,-4.4 -1.5,-3.55 -1.492,-3.512 -1.471,-3.479 -1.438,-3.458 -1.4,-3.45 -1.4,-3.45 -1.362,-3.458 -1.329,-3.479 -1.308,-3.512 -1.3,-3.55 -1.3,-3.55 -1.3,-4.4
  Top Layer region: -0.7,-4.4 -0.7,-3.55 -0.692,-3.512 -0.671,-3.479 -0.638,-3.458 -0.6,-3.45 -0.6,-3.45 -0.562,-3.458 -0.529,-3.479 -0.508,-3.512 -0.5,-3.55 -0.5,-3.55 -0.5,-4.4
  silkscreen extent -4.62,-4.08 4.08,4.08, body extent -4.5,-4.5 4.5,4.5, height 0.25
RTE0016C-MFG [mm]
  rrect42% 0.6x0.24 smd paste+0 mask+0: 1(-1.4,0.75) 2(-1.4,0.25) 3(-1.4,-0.25) 4(-1.4,-0.75) 9(1.4,-0.75) 10(1.4,-0.25) 11(1.4,0.25) 12(1.4,0.75)
  rrect42% 0.24x0.6 smd paste+0 mask+0: 5(-0.75,-1.4) 6(-0.25,-1.4) 7(0.25,-1.4) 8(0.75,-1.4) 13(0.75,1.4) 14(0.25,1.4) 15(-0.25,1.4) 16(-0.75,1.4)
  rrect6% 1.68x1.68 smd paste-1000 mask+0: 17(0,0)
  silkscreen extent -2.37,-1.55 1.55,1.55, body extent -1.8,-1.8 1.8,1.8, height 0.25
RTE0016D [mm] "QFN, 16-Leads, Body 3x3mm, Pitch 0.5mm"
  oval 0.6x0.24 smd: 1(-1.4,0.75) 2(-1.4,0.25) 3(-1.4,-0.25) 4(-1.4,-0.75) 9(1.4,-0.75) 10(1.4,-0.25) 11(1.4,0.25) 12(1.4,0.75)
  oval 0.24x0.6 smd: 5(-0.75,-1.4) 6(-0.25,-1.4) 7(0.25,-1.4) 8(0.75,-1.4) 13(0.75,1.4) 14(0.25,1.4) 15(-0.25,1.4) 16(-0.75,1.4)
  rect 0.8x0.8 smd paste-0.85: 17(0,0)
  silkscreen extent -1.72,-1.73 1.72,1.73, body extent -1.57,-1.57 1.58,1.58, height 0.81
Samtec_HTSW-102-07-G-S [mm] "Samtec 100mil, 1x2, 230 mil above insulator"
  rrect6% 1.65x1.65 hole 1.016: 1(-1.27,0)
  round 1.65 hole 1.016: 2(1.27,0)
  silkscreen extent -3.3,-1.27 2.54,1.27, body extent -2.54,-1.27 2.54,1.27, height 8.38
Samtec_HTSW-103-07-G-S [mm] "Samtec 100mil, 1x3, 230 mil above insulator"
  rrect6% 1.65x1.65 hole 1.016: 1(-2.54,0)
  round 1.65 hole 1.016: 2(0,0) 3(2.54,0)
  silkscreen extent -4.57,-1.27 3.81,1.27, body extent -3.81,-1.27 3.81,1.27, height 8.38
Samtec_QTH-030-01-x-D-A [mil] "Header (Shrouded), 19.7mil, 30x2, SMT"
  rect 12x57 smd: 1(-285.7,121.5) 2(-285.7,-121.5) 3(-266,121.5) 4(-266,-121.5) 5(-246.3,121.5) 6(-246.3,-121.5) 7(-226.6,121.5) 8(-226.6,-121.5) 9(-206.9,121.5) 10(-206.9,-121.5) 11(-187.2,121.5) 12(-187.2,-121.5) 13(-167.5,121.5) 14(-167.5,-121.5) 15(-147.8,121.5) 16(-147.8,-121.5) 17(-128.1,121.5) 18(-128.1,-121.5) 19(-108.4,121.5) 20(-108.4,-121.5) 21(-88.7,121.5) 22(-88.7,-121.5) 23(-69,121.5) 24(-69,-121.5) 25(-49.3,121.5) 26(-49.3,-121.5) 27(-29.6,121.5) 28(-29.6,-121.5) 29(-9.9,121.5) 30(-9.9,-121.5) 31(9.8,121.5) 32(9.8,-121.5) 33(29.5,121.5) 34(29.5,-121.5) 35(49.2,121.5) 36(49.2,-121.5) 37(68.9,121.5) 38(68.9,-121.5) 39(88.6,121.5) 40(88.6,-121.5) 41(108.3,121.5) 42(108.3,-121.5) 43(128,121.5) 44(128,-121.5) 45(147.7,121.5) 46(147.7,-121.5) 47(167.4,121.5) 48(167.4,-121.5) 49(187.1,121.5) 50(187.1,-121.5) 51(206.8,121.5) 52(206.8,-121.5) 53(226.5,121.5) 54(226.5,-121.5) 55(246.2,121.5) 56(246.2,-121.5) 57(265.9,121.5) 58(265.9,-121.5) 59(285.6,121.5) 60(285.6,-121.5)
  round 28 hole 40 unplated: MH1(-364,80) MH2(364,80)
  rect 100x25 smd: MP1(-332.7,0) MP4(332.3,0)
  rect 185x25 smd: MP2(-125.2,0) MP3(124.8,0)
  silkscreen extent -394,-118 394,131, body extent -394,-140 394,140, height 170
SM_RADIAL_F [mm] "8 x 10.2mm:  Panasonic F"
  rect 4x2 smd: 1(-3.55,0) 2(3.55,0)
  silkscreen extent -4.25,-4.25 4.25,4.25, body extent -4.25,-4.25 4.25,4.25, height 10.5
SOT-23 [mm] "SOT23, 3-Leads, Body 2.9x1.3mm, Pitch 0.95mm, Lead Span 2.5mm, IPC Medium Density"
  rrect50% 1x0.6 smd: 1(-1.2,0.95) 2(-1.2,-0.95) 3(1.2,0)
  silkscreen extent -1.62,-1.5 0.7,1.5, body extent -1.16,-1.45 1.21,1.45, height 1
TI_Stacked_Overlay_Small [mil]
  silkscreen extent -418,-98 418,98
TP_SM_1MM [mm] "1mm Test Point, SMT"
  round 1 smd paste-0.5: 1(0,0)
TSW-102-07-G-D [mm] "Samtec 100mil, 2x2, 230 mil above insulator"
  rrect6% 1.65x1.65 hole 1.016: 1(-1.27,-1.27)
  round 1.65 hole 1.016: 2(-1.27,1.27) 3(1.27,-1.27) 4(1.27,1.27)
  silkscreen extent -3.56,-2.54 2.54,2.54, body extent -2.54,-2.54 2.54,2.54, height 8.38
TSW-105-07-G-D [mm] "Samtec 100mil, 2x5, 230 mil above insulator"
  rrect6% 1.65x1.65 hole 1.016: 1(-5.08,-1.27)
  round 1.65 hole 1.016: 2(-5.08,1.27) 3(-2.54,-1.27) 4(-2.54,1.27) 5(0,-1.27) 6(0,1.27) 7(2.54,-1.27) 8(2.54,1.27) 9(5.08,-1.27) 10(5.08,1.27)
  silkscreen extent -7.37,-2.54 6.35,2.54, body extent -6.35,-2.54 6.35,2.54, height 8.38
WEEE_Minimum [mil] "WEEElie bin"
  silkscreen extent -95,-172 99,104
WL-SMCW_GREEN [mm] "WURTH"
  rect 0.8x0.8 smd: 1(-0.8,0) 2(0.8,0)
  silkscreen extent -1.9,-0.8 1.2,0.8, body extent -0.85,-0.45 0.85,0.45, height 0.8
Wurth_60900213421 [mil] "Shunt, 2.54mm, Black"
  round 1 on Mech3: 0(0,0)
  body extent -98,-48 98,48, height 338
Wurth_WA-SMSI [mm] "ROUND STANDOFF M3 STEEL 5MM"
  round 0 hole 4.4 unplated: ""(0,0)
  Top Layer region: -3.711,0 -3.666,-0.581 -3.53,-1.147 -3.307,-1.685 -3.003,-2.182 -2.624,-2.624 -2.182,-3.003 -1.685,-3.307 -1.147,-3.53 -0.581,-3.666 0,-3.711 0.581,-3.666 1.147,-3.53 1.685,-3.307 2.182,-3.003 2.624,-2.624 3.003,-2.182 3.307,-1.685 3.53,-1.147 3.666,-0.581 3.711,0 3.7,0 2.466,0 2.418,-0.481 2.278,-0.944 2.05,-1.37 1.744,-1.744 1.37,-2.05 0.944,-2.278 0.481,-2.418 0,-2.466 -0.481,-2.418 -0.944,-2.278 -1.37,-2.05 -1.744,-1.744 -2.05,-1.37 -2.278,-0.944 -2.418,-0.481 -2.466,0 -2.454,0
  Top Layer region: -3.711,0 -3.666,0.581 -3.53,1.147 -3.307,1.685 -3.003,2.182 -2.624,2.624 -2.182,3.003 -1.685,3.307 -1.147,3.53 -0.581,3.666 0,3.711 0.581,3.666 1.147,3.53 1.685,3.307 2.182,3.003 2.624,2.624 3.003,2.182 3.307,1.685 3.53,1.147 3.666,0.581 3.711,0 3.7,0 2.466,0 2.418,0.481 2.278,0.944 2.05,1.37 1.744,1.744 1.37,2.05 0.944,2.278 0.481,2.418 0,2.466 -0.481,2.418 -0.944,2.278 -1.37,2.05 -1.744,1.744 -2.05,1.37 -2.278,0.944 -2.418,0.481 -2.466,0 -2.454,0
  silkscreen extent -4.1,-4.1 4.1,4.1, body extent -2.99,-2.98 2.99,3, height 5

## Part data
C1 C4 C9 C17: library part CMP-0006632-2, "CAP, CERM, 0.033 uF, 10 V, +/- 10%, X7R, 0402", Cap_Case=0402, Manufacturer=MuRata, Supplier Part Number 1=490-1315-1-ND, TempCo=X7R, Tolerance_%=10%, Value1=Unknown, Value2=10V, ValueDisplayed=0.033uF
C2 C3 C11 C12: library part CMP-0006676-2, "CAP, CERM, 1200 pF, 50 V, +/- 10%, X7R, 0402", Cap_Case=0402, Manufacturer=MuRata, Supplier Part Number 1=490-1304-1-ND, TempCo=X7R, Tolerance_%=10%, Value1=Unknown, Value2=50V, ValueDisplayed=1200pF
C5 C25 C30 C55: library part CMP-0006644-2, "CAP, CERM, 0.015 uF, 16 V, +/- 10%, X7R, 0402", Cap_Case=0402, Manufacturer=MuRata, Supplier Part Number 1=490-1314-1-ND, TempCo=X7R, Tolerance_%=10%, Value1=Unknown, Value2=16V, ValueDisplayed=0.015uF
C6 C124: library part CMP-0007040-4, "CAP, CERM, 1 uF, 25 V, +/- 10%, X7R, 0603", Cap_Case=0603, Manufacturer=TDK, Supplier Part Number 1=445-5956-1-ND, TempCo=X7R, Tolerance_%=10%, Value1=Unknown, Value2=25V, ValueDisplayed=1uF
C7 C26 C27 C28 C29 C125: library part CMP-0006659-2, "CAP, CERM, 0.1 uF, 25 V, +/- 10%, X7R, 0402", Cap_Case=0402, Manufacturer=MuRata, Supplier Part Number 1=490-10698-1-ND, TempCo=X7R, Tolerance_%=10%, Value1=Unknown, Value2=25V, ValueDisplayed=0.1uF
C8: library part CMP-0010723-1, "CAP, AL, 100 uF, 35 V, +/- 20%, 0.16 ohm, AEC-Q200 Grade 2, SMD", Cap_Case=F, Manufacturer=Panasonic, Supplier Part Number 1=PCE3835CT-ND, Tolerance_%=20%, Value1="0.16 ohm", Value2=35V, ValueDisplayed=100uF
C10 C13 C14 C15 C16 C19 C20 C21: library part CMP-0008262-2, "CAP, CERM, 10 uF, 25 V, +/- 10%, X7S, 0805", Cap_Case=0805, Manufacturer=MuRata, Supplier Part Number 1=490-10496-1-ND, TempCo=X7S, Tolerance_%=10%, Value1=Unknown, Value2=25V, ValueDisplayed=10uF
C18 C22 C23 C24: library part CMP-0081010-1, "CAP, CERM, 2.2 µF, 25 V,+/- 20%, X5R, 0402", Cap_Case=0402, Manufacturer=MuRata, Supplier Part Number 1=490-10457-1-ND, TempCo=X5R, Tolerance_%=20%, Value2=25V, ValueDisplayed=2.2µF
C31 C32 C33 C34 C35 C36 C37 C38: library part CMP-0007890-2, "CAP, CERM, 22 uF, 10 V, +/- 20%, X7S, 0805", Cap_Case=0805, Manufacturer=TDK, Supplier Part Number 1=445-14560-1-ND, TempCo=X7S, Tolerance_%=20%, Value1="0.00205 ohm", Value2=10V, ValueDisplayed=22uF
C39 C40 C41 C42 C43 C44 C45 C46 C47 C48 C49 C50 C51 C52 C53 C54 C56 C57 C58 C59 C60 C61 C62 C63: library part CMP-0082099-1, "CAP, CERM, 47 µF, 10 V,+/- 20%, X7R, 1210", Cap_Case=1210, Manufacturer="Taiyo Yuden", Supplier Part Number 1=587-5922-1-ND, TempCo=X7R, Tolerance_%=20%, Value1="0.001 ohm", Value2=10V, ValueDisplayed=47µF
C64 C65 C66 C67 C75 C76 C77 C78 C79 C80 C81 C84 C89 C90 C93 C100 C107 C109 C112 C113 C114 C115 C126 C127: library part CMP-0006591-2, "CAP, CERM, 0.1 uF, 16 V, +/- 10%, X5R, 0402", Cap_Case=0402, Manufacturer=MuRata, Supplier Part Number 1=490-5415-1-ND, TempCo=X5R, Tolerance_%=10%, Value1=Unknown, Value2=16V, ValueDisplayed=0.1uF
C68 C69 C71 C73 C74 C82 C88 C91 C92 C95 C96 C98 C101 C103 C106 C108: library part CMP-0076705-3, "CAP, CERM, 1 µF, 25 V,+/- 10%, X7R, AEC-Q200 Grade 1, 0603", Cap_Case=1.6x0.8x0.8mm, Manufacturer=TDK, Supplier Part Number 1=445-6931-1-ND, TempCo=X7R, Tolerance_%=10%, Value2=25V, ValueDisplayed=1µF
C70 C72 C83: library part CMP-0007344-5, "CAP, CERM, 10 uF, 25 V, +/- 20%, X5R, 0603", Cap_Case=0603, Manufacturer=MuRata, Supplier Part Number 1=490-7202-1-ND, TempCo=X5R, Tolerance_%=20%, Value1=Unknown, Value2=25V, ValueDisplayed=10uF
C85 C87: library part CMP-0009780-1, "CAP, CERM, 4.7 uF, 6.3 V, +/- 20%, X5R, 0201", Cap_Case=0201, Manufacturer=MuRata, Supplier Part Number 1=490-13230-1-ND, TempCo=X5R, Tolerance_%=20%, Value1=Unknown, Value2=6.3V, ValueDisplayed=4.7uF
C86: library part CMP-0007497-5, "CAP, CERM, 10 uF, 10 V, +/- 20%, X7R, 0603", Cap_Case=0603, Manufacturer=MuRata, Supplier Part Number 1=81-GRM188Z71A106MA3D, TempCo=X7R, Tolerance_%=20%, Value1=Unknown, Value2=10V, ValueDisplayed=10uF
C94: library part CMP-0076705-3, "CAP TANT POLY 2.2UF 10V 0603", Cap_Case=1.6x0.8x0.8mm, Manufacturer="KYOCERA AVX", TempCo=X7R, Tolerance_%=20%, Value2=10V, ValueDisplayed=2.2uF
C97 C104 C105: library part CMP-0085817-1, "CAP, CERM, 22 µF, 35 V,+/- 20%, X5R, 1210", Cap_Case=1210, Manufacturer="Taiyo Yuden", TempCo=X5R, Tolerance_%=20%, Value2=35V, ValueDisplayed=22µF
C99 C102: library part CMP-0007469-4, "CAP, CERM, 0.1 uF, 100 V, +/- 10%, X7R, 0603", Cap_Case=0603, Manufacturer=MuRata, Supplier Part Number 1=490-3285-1-ND, TempCo=X7R, Tolerance_%=10%, Value1=Unknown, Value2=100V, ValueDisplayed=0.1uF
C110: library part CMP-0078265-1, "CAP, CERM, 0.22 µF, 16 V,+/- 10%, X7R, AEC-Q200 Grade 1, 0402", Cap_Case=0402, Manufacturer=MuRata, Supplier Part Number 1=490-10671-1-ND, TempCo=X7R, Tolerance_%=10%, Value2=16V, ValueDisplayed=0.22µF
C111: library part CMP-0006421-1, "CAP, CERM, 150 pF, 50 V, +/- 5%, C0G/NP0, 0402", Cap_Case=0402, Manufacturer=MuRata, Supplier Part Number 1=490-3229-1-ND, TempCo=C0G/NP0, Tolerance_%=5%, Value1=Unknown, Value2=50V, ValueDisplayed=150pF
C116 C117 C120 C121: library part CMP-0085302-1, "CAP, CERM, 1 µF, 16 V,+/- 10%, X7R, AEC-Q200 Grade 1, 0603", Cap_Case=0603, Manufacturer="Samsung Electro-Mechanics", TempCo=X7R, Tolerance_%=10%, Value2=16V, ValueDisplayed=1µF
C118 C119 C122 C123: library part CMP-0007388-4, "CAP, CERM, 0.022 uF, 16 V, +/- 10%, X7R, 0603", Cap_Case=0603, Manufacturer=MuRata, Supplier Part Number 1=490-1527-1-ND, TempCo=X7R, Tolerance_%=10%, Value1=Unknown, Value2=16V, ValueDisplayed=0.022uF
D1 D2 D3 D4: library part CMP-0002894-2, "LED, Green, SMD", Color=green, Manufacturer="Wurth Elektronik", Value1=W, Value2=2V
D5 D6 D7 D8 D9 D10 D11 D12: library part CMP-0126888-1, "Diode Switching 100V 0.15A 2-Pin DFN T/R", Digikey Part Number=1N4148WL2-TPMSCT-ND, Forward Current=150mA, Manufacturer=MCC, Max Surge Forward Current=4A, Mouser Part Number=833-1N4148WL2-TP, Operating Temperature Range="-65°C to +150°C", Peak Reverse Current=5uA, ValueDisplayed=1.5pF
FID1 FID2 FID3: library part CMP-0077181-1, "Fiducial mark.  There is nothing to buy or mount.", Manufacturer=N/A
H1 H5 H7 H10: library part CMP-0003610-1, "Standoff, Hex, 0.5\"L #4-40 Nylon", Manufacturer=Keystone, Supplier Part Number 1=36-1902C-ND
H2 H4: library part CMP-0003785-1, "ROUND STANDOFF M3 STEEL 5MM", Manufacturer="Wurth Elektronik", Supplier Part Number 1=732-5272-1-ND
H3 H6 H8 H11: library part CMP-0003617-1, "Machine Screw, Round, #4-40 x 1/4, Nylon, Philips panhead", Manufacturer="B&F Fastener Supply", Supplier Part Number 1=H542-ND
J1 J2: library part CMP-0075410-2, "Header, 100mil, 5x2, Gold, TH", Color=Black, Current_A=6.3A, Manufacturer=Samtec, Supplier Part Number 1=SAM1028-05-ND, Voltage_V=550V
J3: library part CMP-0075484-1, "Header, 100mil, 3x1, Gold, TH", Manufacturer=Samtec, Supplier Part Number 1=HTSW-103-07-G-S-ND
J4: library part CMP-0075483-1, "Header, 100mil, 2x1, Gold, TH", Manufacturer=Samtec, Supplier Part Number 1=SAM8736-ND
J5: library part CMP-0003814-2, "C2000 controlCARD-120HSEC connector, SMT", Manufacturer=Samtec
J6: library part CMP-0003859-2, "C2000 controlCARD-180HSEC (60-pin addon) connector, SMT", Manufacturer=Samtec
J7: library part CMP-0075558-2, "Header(Shrouded), 19.7mil, 30x2, Gold, SMT", Manufacturer=Samtec, PartNumber=QTH-030-01-L-D-A, Supplier Part Number 1=SAM8185-ND
J8 J9 J14 J15: library part CMP-0075404-1, "Header, 100mil, 2x2, Gold, TH", Color=Black, Current_A=6.3A, Manufacturer=Samtec, Supplier Part Number 1=SAM1028-02-ND, Voltage_V=550V
J10 J11 J12 J13 J16 J17 J18 J19 J21 J22: "Standard Banana Jack, Uninsulated, 5.5mm", Manufacturer=Keystone, PartNumber=575-4, Supplier Part Number 1=36-575-4-ND
J20: library part CMP-0055462-1, "Connector, DC Jack 2.1X5.5 mm, TH", Manufacturer="CUI Inc.", Supplier Part Number 1=CP-102A-ND
L1: library part CMP-0003369-1, "Ferrite Bead, 1000 ohm @ 100 MHz, 1.5 A, 1806", Manufacturer=MuRata, Supplier Part Number 1=490-1061-1-ND, Value1="0.09 ohm", Value2=1.5A, ValueDisplayed="1000 ohm"
L2: library part CMP-0061372-2, "Inductor, Shielded Drum Core, Ferrite, 18 uH, 0.8 A, 0.55 ohm, SMD", Manufacturer=Coilcraft, Value1="0.55 ohm", Value2=0.8A, ValueDisplayed=18uH
LBL1: library part CMP-0003625-1, "Thermal Transfer Printable Labels, 0.650\" W x 0.200\" H - 10,000 per roll", Manufacturer=Brady, Supplier Part Number 1=97C5133
Logo1: library part CMP-0074837-2, "IEC 61010-1 Hot Surface Warning", Manufacturer="Texas Instruments"
Logo2: library part CMP-0074838-1, "Texas Instrument Corporate Signature"
Logo3: library part CMP-0074844-1
Logo4: library part CMP-0074847-1, "FCC_disclaimer"
Logo5: library part CMP-0074769-3, Manufacturer="Texas Instruments"
NT1: library part CMP-0078142-6, "Single point connection between nets.", Manufacturer=N/A
Q1 Q2 Q7 Q8: library part CMP-0085603-1, "MOSFET, N-CH, 60 V, 0.115 A, AEC-Q101, SOT-23", Alternate Manufacturer=None, Manufacturer="Diodes Inc.", Value1="? ohm", Value2="0.223 nC"
Q3 Q4 Q9 Q10: library part CMP-0126605-1, "Optoisolator Photovoltaic Output 1500Vrms 1 Channel 4-SSOP", Digikey Part Number=255-3874-1-ND, Forward Current=50mA, Manufacturer=Panasonic, Mouser Part Number=769-APV2111VY, Operating Temperature Range="-40°C to +85°C", Power_TotalModule=75mW, Voltage_Isolation_Vrms=1.5kV
Q5 Q6 Q11 Q12: library part CMP-0127063-1, "NexFET Power MOSFET Dual N-Channel 30V 10A 8-Pin VSON T/R", Digikey Part Number=296-51022-1-ND, Drain To Source Breakdown Voltage=30V, Input Capacitance At Vds="782pF @ 15V", Manufacturer="Texas Instruments", Mouser Part Number=595-CSD87503Q3E, Operating Temperature Range="-55°C to +150°C", Power_W=2.6W, Pulse Drain Current=89A, Typ Forward Diode Voltage=0.75V
R1 R7: library part CMP-0026225-2, "RES, 29.4 k, 1%, 0.063 W, AEC-Q200 Grade 0, 0402", Manufacturer=Vishay-Dale, Power_W=63mW, Supplier Part Number 1=541-29.4KLCT-ND, TempCo="100 ppm/C", Tolerance_%=1%, Value2=0.063W, Value_Code=29k4, ValueDisplayed=29.4k
R2 R8: library part CMP-0026367-2, "RES, 40.2 k, 1%, 0.063 W, AEC-Q200 Grade 0, 0402", Manufacturer=Vishay-Dale, Power_W=63mW, Supplier Part Number 1=541-40.2KLCT-ND, TempCo="100 ppm/C", Tolerance_%=1%, Value2=0.063W, Value_Code=40k2, ValueDisplayed=40.2k
R3 R4 R9 R10: library part CMP-0025960-3, "RES, 10.5 k, 1%, 0.063 W, AEC-Q200 Grade 0, 0402", Manufacturer=Vishay-Dale, Power_W=63mW, Supplier Part Number 1=541-10.5KLCT-ND, TempCo="100 ppm/C", Tolerance_%=1%, Value2=0.063W, Value_Code=10k5, ValueDisplayed=10.5k
R5 R6 R11 R12 R14 R15 R18 R19 R86 R87 R88 R100 R101 R187: library part CMP-0023653-3, "RES, 10.0 k, 0.1%, 0.1 W, 0603", Manufacturer="Yageo America", Power_W=100mW, TempCo="25 ppm/C", Tolerance_%=0.1%, Value2=0.1W, Value_Code=10k0, ValueDisplayed=10.0k
R13 R16 R17 R20 R21 R26 R29 R32 R39 R177 R178: library part CMP-0025958-3, "RES, 10.0 k, 1%, 0.063 W, AEC-Q200 Grade 0, 0402", Manufacturer=Vishay-Dale, Power_W=63mW, Supplier Part Number 1=541-10.0KLCT-ND, TempCo="100 ppm/C", Tolerance_%=1%, Value2=0.063W, Value_Code=10k0, ValueDisplayed=10.0k
R22 R23 R24 R25 R42 R43 R44 R45 R46 R47 R48 R49 R50 R51 R60 R61 R62 R63 R64 R65 R66 R67 R68 R69 R70 R71 R72 R73 R74 R76 R77 R78 R79 R80 R81 R82 R83 R84 R85 R89 R90 R91 R92 R93 R94 R95 R96 R97 R98 R102 R103 R104 R105 R106 R183 R184 R185 R186 R189 R190 R191 R192: library part CMP-0026822-3, "RES, 0, 5%, 0.063 W, AEC-Q200 Grade 0, 0402", Manufacturer=Vishay-Dale, Power_W=63mW, Supplier Part Number 1=541-0.0JCT-ND, TempCo="200 ppm/C", Tolerance_%=5%, Value2=0.063W, Value_Code=0000, ValueDisplayed=0
R27 R30 R33 R38: library part CMP-0026097-2, "RES, 1.87 k, 1%, 0.063 W, AEC-Q200 Grade 0, 0402", Manufacturer=Vishay-Dale, Power_W=63mW, Supplier Part Number 1=541-1.87KLCT-ND, TempCo="100 ppm/C", Tolerance_%=1%, Value2=0.063W, Value_Code=1k87, ValueDisplayed=1.87k
R28 R34 R36 R52: library part CMP-0026414-2, "RES, 4.99 k, 1%, 0.063 W, AEC-Q200 Grade 0, 0402", Manufacturer=Vishay-Dale, Power_W=63mW, Supplier Part Number 1=541-4.99KLCT-ND, TempCo="100 ppm/C", Tolerance_%=1%, Value2=0.063W, Value_Code=4k99, ValueDisplayed=4.99k
R31 R37 R41 R53 R54 R56 R57 R59: library part CMP-0022170-4, "RES, 1.00, 1%, 0.1 W, AEC-Q200 Grade 0, 0603", Manufacturer=Vishay-Dale, Power_W=100mW, Supplier Part Number 1=52K8059, TempCo="100 ppm/C", Tolerance_%=1%, Value2=0.1W, Value_Code=1R00, ValueDisplayed=1.00
R35 R40 R55 R58: library part CMP-0126009-1, "4 mOhms ±1% 2W Chip Resistor 2512 (6432 Metric) Anti-Sulfur, Automotive AEC-Q200, Current Sense Metal Element", Digikey Part Number=1712-TLRP3A20CR080FTECT-ND, Manufacturer="TE Connectivity", Mouser Part Number=279-TLRP3A20CR080FTE, Operating Temperature Range="-55°C to +170°C", Power_W=2W, Supplier Part Number 1=1712-TLRP3A20CR004FTECT-ND, TempCo=25ppm/°C, Tolerance_%=1%
R75: library part CMP-0026632-2, "RES, 0.22, 1%, 0.125 W, AEC-Q200 Grade 0, 0402", Manufacturer=Panasonic, Power_W=125mW, Supplier Part Number 1=P.22AKCT-ND, TempCo="250 ppm/C", Tolerance_%=1%, Value2=0.125W, Value_Code=R220, ValueDisplayed=0.22
R99: library part CMP-0024365-1, "RES, 5.05 k, 0.1%, 0.1 W, 0603", Manufacturer="Yageo America", Power_W=100mW, TempCo="25 ppm/C", Tolerance_%=0.1%, Value2=0.1W, Value_Code=5k05, ValueDisplayed=5.05k
R107 R108 R111 R114 R115: library part CMP-0025729-4, "RES, 1.0 k, 5%, 0.1 W, AEC-Q200 Grade 0, 0603", Manufacturer=Vishay-Dale, Power_W=100mW, Supplier Part Number 1=541-1.0KGCT-ND, TempCo="200 ppm/C", Tolerance_%=5%, Value2=0.1W, Value_Code=1k00, ValueDisplayed=1.0k
R109: library part CMP-0025986-3, "RES, 124 k, 1%, 0.063 W, AEC-Q200 Grade 0, 0402", Manufacturer=Vishay-Dale, Power_W=63mW, Supplier Part Number 1=541-124KLCT-ND, TempCo="100 ppm/C", Tolerance_%=1%, Value2=0.063W, Value_Code=124k
R110: library part CMP-0026178-2, "RES, 22.1 k, 1%, 0.063 W, AEC-Q200 Grade 0, 0402", Manufacturer=Vishay-Dale, Power_W=63mW, Supplier Part Number 1=541-22.1KLCT-ND, TempCo="100 ppm/C", Tolerance_%=1%, Value2=0.063W, Value_Code=22k1, ValueDisplayed=22.1k
R112 R113: library part CMP-0094724-1, "Jumper 0.25W, 1/4W Chip Resistor 1206 (3216 Metric) - Thick Film", Digikey Part Number=541-4170-1-ND, Manufacturer=Vishay, Mouser Part Number=71-CRCW12060000Z0EAC, Operating Temperature Range="-55°C to +155°C", Power_W=250mW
